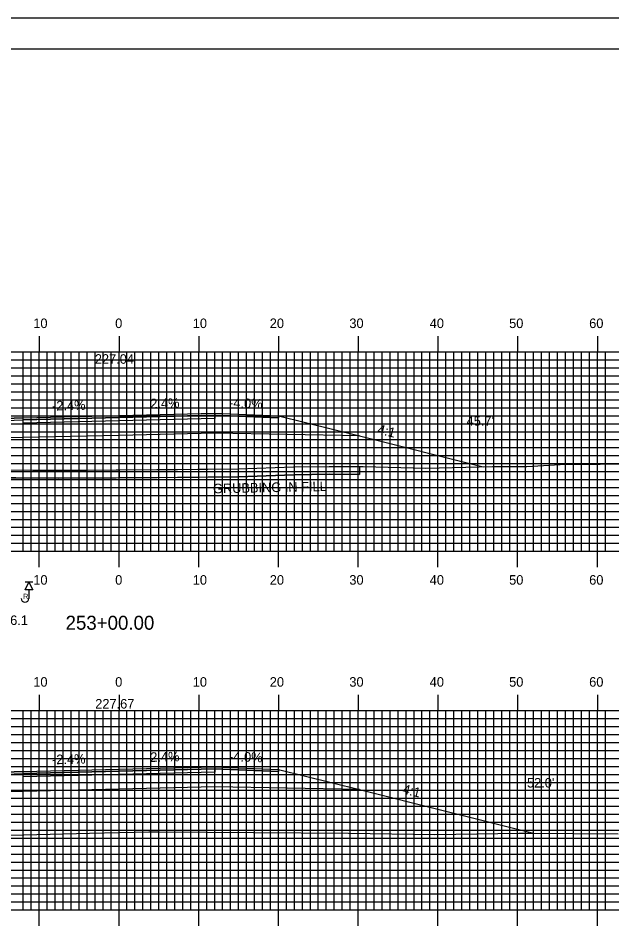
# Model space of a CAD drawing. Extents: x 1804290 to 1804634, y 442591 to 442811.
# Drawn here: x 1804443.5 to 1804518, y 442696.2 to 442810.5 of the extents above; entities that cross this region are included whole.
import ezdxf

# ---------------------------------------------------------------- set-up
doc = ezdxf.new("R2010")
doc.units = 0
for name, color, linetype in [('ANNOTATION', 7, 'Continuous'), ('BORDER', 7, 'Continuous'), ('BORING - REFUSAL', 7, 'Continuous'), ('D_Roadway_Centerline', 7, 'Continuous'), ('D_Roadway_Centerline_Text', 7, 'Continuous'), ('D_Roadway_Edge_Shoulder', 7, 'Continuous'), ('D_Roadway_Edge_TW', 7, 'Continuous'), ('D_Roadway_Pavement', 7, 'Continuous'), ('D_Roadway_SlopeLines', 7, 'Continuous'), ('D_Roadway_SubGrade', 7, 'Continuous'), ('D_Text_Standard', 7, 'Continuous'), ('GRUBBING IN FILL', 7, 'Continuous'), ('H_V ANNOTATION', 7, 'Continuous'), ('MAJOR', 7, 'Continuous'), ('MINOR', 7, 'Continuous'), ('PLOT BOUNDARY', 7, 'Continuous'), ('S_Roadway_Centerline', 7, 'Continuous')]:
    doc.layers.add(name, color=color, linetype=linetype)

msp = doc.modelspace()

# ---------------------------------------------------------------- linework, layer by layer
at = {"layer": 'BORDER'}
msp.add_lwpolyline([(1804306.57, 442596.67), (1804626.57, 442596.67), (1804626.57, 442806.67), (1804306.57, 442806.67)], close=True, dxfattribs=at)
at = {"layer": 'BORING - REFUSAL'}
for p, q in [((1804445.35, 442739.77), (1804444.39, 442739.77)), ((1804444.87, 442738.81), (1804444.87, 442737.75))]:
    msp.add_line(p, q, dxfattribs=at)
msp.add_lwpolyline([(1804444.87, 442739.77), (1804445.35, 442738.81), (1804444.39, 442738.81)], close=True, dxfattribs=at)
msp.add_arc((1804444.38, 442737.75), 0.485, 180, 0, dxfattribs=at)
at = {"layer": 'D_Roadway_Centerline'}
for points in [[(1804410.07, 442753.57), (1804424.17, 442757.1), (1804425.99, 442757.55), (1804436.17, 442760.1), (1804444.17, 442760.42), (1804456.17, 442760.71), (1804468.17, 442760.99), (1804476.17, 442760.67), (1804486.34, 442758.13), (1804501.85, 442754.25)], [(1804404.33, 442707.76), (1804424.17, 442712.72), (1804425.99, 442713.18), (1804436.17, 442715.72), (1804444.17, 442716.04), (1804456.17, 442716.33), (1804468.17, 442716.62), (1804476.17, 442716.3), (1804486.34, 442713.76), (1804508.15, 442708.3)]]:
    msp.add_lwpolyline(points, dxfattribs=at)
at = {"layer": 'D_Roadway_Edge_Shoulder'}
for points in [[(1804468.17, 442760.99), (1804476.17, 442760.67), (1804476.17, 442760.42), (1804468.17, 442760.74)], [(1804444.17, 442760.42), (1804436.17, 442760.1), (1804436.17, 442759.85), (1804444.17, 442760.17)], [(1804468.17, 442716.62), (1804476.17, 442716.3), (1804476.17, 442716.05), (1804468.17, 442716.37)], [(1804444.17, 442716.04), (1804436.17, 442715.72), (1804436.17, 442715.47), (1804444.17, 442715.79)]]:
    msp.add_lwpolyline(points, close=True, dxfattribs=at)
at = {"layer": 'D_Roadway_Edge_TW'}
for points in [[(1804444.17, 442760.17), (1804444.17, 442760.42), (1804456.17, 442760.71), (1804468.17, 442760.99), (1804468.17, 442760.74), (1804456.17, 442760.46)], [(1804444.17, 442715.79), (1804444.17, 442716.04), (1804456.17, 442716.33), (1804468.17, 442716.62), (1804468.17, 442716.37), (1804456.17, 442716.08)]]:
    msp.add_lwpolyline(points, close=True, dxfattribs=at)
at = {"layer": 'D_Roadway_Pavement'}
for points in [[(1804444.17, 442759.75), (1804444.17, 442760.17), (1804456.17, 442760.46), (1804468.17, 442760.74), (1804468.17, 442760.33), (1804456.17, 442760.04)], [(1804444.17, 442715.38), (1804444.17, 442715.79), (1804456.17, 442716.08), (1804468.17, 442716.37), (1804468.17, 442715.95), (1804456.17, 442715.66)]]:
    msp.add_lwpolyline(points, close=True, dxfattribs=at)
at = {"layer": 'D_Roadway_SlopeLines'}
for points in [[(1804476.17, 442760.67), (1804486.34, 442758.13), (1804501.85, 442754.25)], [(1804476.17, 442716.3), (1804486.34, 442713.76), (1804508.15, 442708.3)]]:
    msp.add_lwpolyline(points, dxfattribs=at)
at = {"layer": 'D_Roadway_SubGrade'}
for points in [[(1804444.17, 442757.92), (1804425.99, 442757.55), (1804436.17, 442760.1), (1804436.17, 442759.85), (1804444.17, 442760.17), (1804456.17, 442760.46), (1804468.17, 442760.74), (1804476.17, 442760.42), (1804476.17, 442760.67), (1804486.34, 442758.13), (1804468.17, 442758.49), (1804456.17, 442758.21)], [(1804444.17, 442713.54), (1804425.99, 442713.18), (1804436.17, 442715.72), (1804436.17, 442715.47), (1804444.17, 442715.79), (1804456.17, 442716.08), (1804468.17, 442716.37), (1804476.17, 442716.05), (1804476.17, 442716.3), (1804486.34, 442713.76), (1804468.17, 442714.12), (1804456.17, 442713.83)]]:
    msp.add_lwpolyline(points, close=True, dxfattribs=at)
at = {"layer": 'GRUBBING IN FILL'}
msp.add_line((1804486.34, 442754.29), (1804486.34, 442753.29), dxfattribs=at)
msp.add_line((1804486.34, 442754.29), (1804486.34, 442753.29), dxfattribs=at)
for points in [[(1804425.99, 442753.01), (1804425.99, 442754.01), (1804431.89, 442754.11), (1804437, 442753.99), (1804442.11, 442753.87), (1804445.35, 442753.85), (1804452.2, 442753.85), (1804456.17, 442753.87), (1804456.17, 442752.87), (1804452.2, 442752.85), (1804448.59, 442752.84), (1804445.34, 442752.85), (1804436.99, 442752.99), (1804431.89, 442753.11)], [(1804425.99, 442753.01), (1804425.99, 442754.01), (1804431.89, 442754.11), (1804437, 442753.99), (1804442.11, 442753.87), (1804445.35, 442753.85), (1804452.2, 442753.85), (1804456.17, 442753.87), (1804456.17, 442752.87), (1804452.2, 442752.85), (1804448.59, 442752.84), (1804445.34, 442752.85), (1804436.99, 442752.99), (1804431.89, 442753.11)], [(1804456.17, 442753.87), (1804463.49, 442753.94), (1804471.17, 442754.01), (1804478.07, 442754.25), (1804482.53, 442754.32), (1804484.66, 442754.31), (1804486.34, 442754.29), (1804486.34, 442753.29), (1804484.44, 442753.31), (1804482.54, 442753.32), (1804478.09, 442753.25), (1804474.64, 442753.13), (1804471.19, 442753.01), (1804463.51, 442752.94), (1804456.17, 442752.87)], [(1804456.17, 442753.87), (1804463.49, 442753.94), (1804471.17, 442754.01), (1804478.07, 442754.25), (1804482.53, 442754.32), (1804484.66, 442754.31), (1804486.34, 442754.29), (1804486.34, 442753.29), (1804484.44, 442753.31), (1804482.54, 442753.32), (1804478.09, 442753.25), (1804474.64, 442753.13), (1804471.19, 442753.01), (1804463.51, 442752.94), (1804456.17, 442752.87)]]:
    msp.add_lwpolyline(points, close=True, dxfattribs=at)
msp.add_lwpolyline([(1804425.99, 442753.01), (1804431.89, 442753.11), (1804442.1, 442752.87), (1804448.59, 442752.84), (1804455.82, 442752.87), (1804471.19, 442753.01), (1804478.09, 442753.25), (1804482.54, 442753.32), (1804486.34, 442753.29)], dxfattribs=at)
msp.add_lwpolyline([(1804425.99, 442753.01), (1804431.89, 442753.11), (1804442.1, 442752.87), (1804448.59, 442752.84), (1804455.82, 442752.87), (1804471.19, 442753.01), (1804478.09, 442753.25), (1804482.54, 442753.32), (1804486.34, 442753.29)], dxfattribs=at)
at = {"layer": 'MAJOR'}
for p, q in [((1804446.17, 442770.67), (1804446.17, 442768.67)), ((1804456.17, 442770.67), (1804456.17, 442768.67)), ((1804466.17, 442770.67), (1804466.17, 442768.67)), ((1804476.17, 442770.67), (1804476.17, 442768.67)), ((1804486.17, 442770.67), (1804486.17, 442768.67)), ((1804496.17, 442770.67), (1804496.17, 442768.67)), ((1804506.17, 442770.67), (1804506.17, 442768.67)), ((1804516.17, 442770.67), (1804516.17, 442768.67)), ((1804316.17, 442768.67), (1804596.17, 442768.67)), ((1804316.17, 442768.67), (1804596.17, 442768.67)), ((1804446.17, 442743.67), (1804446.17, 442768.67)), ((1804456.17, 442743.67), (1804456.17, 442768.67)), ((1804466.17, 442743.67), (1804466.17, 442768.67)), ((1804476.17, 442743.67), (1804476.17, 442768.67)), ((1804486.17, 442743.67), (1804486.17, 442768.67)), ((1804496.17, 442743.67), (1804496.17, 442768.67)), ((1804506.17, 442743.67), (1804506.17, 442768.67)), ((1804516.17, 442743.67), (1804516.17, 442768.67)), ((1804316.17, 442763.67), (1804596.17, 442763.67)), ((1804316.17, 442758.67), (1804596.17, 442758.67)), ((1804316.17, 442753.67), (1804596.17, 442753.67)), ((1804316.17, 442748.67), (1804596.17, 442748.67)), ((1804316.17, 442743.67), (1804596.17, 442743.67)), ((1804316.17, 442743.67), (1804596.17, 442743.67)), ((1804446.17, 442741.66), (1804446.17, 442743.67)), ((1804456.17, 442741.66), (1804456.17, 442743.67)), ((1804466.17, 442741.66), (1804466.17, 442743.67)), ((1804476.17, 442741.66), (1804476.17, 442743.67)), ((1804486.17, 442741.66), (1804486.17, 442743.67)), ((1804496.17, 442741.66), (1804496.17, 442743.67)), ((1804506.17, 442741.66), (1804506.17, 442743.67)), ((1804516.17, 442741.66), (1804516.17, 442743.67)), ((1804446.17, 442725.67), (1804446.17, 442723.67)), ((1804456.17, 442725.67), (1804456.17, 442723.67)), ((1804466.17, 442725.67), (1804466.17, 442723.67)), ((1804476.17, 442725.67), (1804476.17, 442723.67)), ((1804486.17, 442725.67), (1804486.17, 442723.67)), ((1804496.17, 442725.67), (1804496.17, 442723.67)), ((1804506.17, 442725.67), (1804506.17, 442723.67)), ((1804516.17, 442725.67), (1804516.17, 442723.67)), ((1804316.17, 442723.67), (1804596.17, 442723.67)), ((1804316.17, 442723.67), (1804596.17, 442723.67)), ((1804446.17, 442698.67), (1804446.17, 442723.67)), ((1804456.17, 442698.67), (1804456.17, 442723.67)), ((1804466.17, 442698.67), (1804466.17, 442723.67)), ((1804476.17, 442698.67), (1804476.17, 442723.67)), ((1804486.17, 442698.67), (1804486.17, 442723.67)), ((1804496.17, 442698.67), (1804496.17, 442723.67)), ((1804506.17, 442698.67), (1804506.17, 442723.67)), ((1804516.17, 442698.67), (1804516.17, 442723.67)), ((1804316.17, 442718.67), (1804596.17, 442718.67)), ((1804316.17, 442713.67), (1804596.17, 442713.67)), ((1804316.17, 442708.67), (1804596.17, 442708.67)), ((1804316.17, 442703.67), (1804596.17, 442703.67)), ((1804316.17, 442698.67), (1804596.17, 442698.67)), ((1804316.17, 442698.67), (1804596.17, 442698.67)), ((1804446.17, 442696.66), (1804446.17, 442698.67)), ((1804456.17, 442696.66), (1804456.17, 442698.67)), ((1804466.17, 442696.66), (1804466.17, 442698.67)), ((1804476.17, 442696.66), (1804476.17, 442698.67)), ((1804486.17, 442696.66), (1804486.17, 442698.67)), ((1804496.17, 442696.66), (1804496.17, 442698.67)), ((1804506.17, 442696.66), (1804506.17, 442698.67)), ((1804516.17, 442696.66), (1804516.17, 442698.67))]:
    msp.add_line(p, q, dxfattribs=at)
at = {"layer": 'MINOR'}
for p, q in [((1804316.17, 442767.67), (1804596.17, 442767.67)), ((1804444.17, 442743.67), (1804444.17, 442768.67)), ((1804445.17, 442743.67), (1804445.17, 442768.67)), ((1804447.17, 442743.67), (1804447.17, 442768.67)), ((1804448.17, 442743.67), (1804448.17, 442768.67)), ((1804449.17, 442743.67), (1804449.17, 442768.67)), ((1804450.17, 442743.67), (1804450.17, 442768.67)), ((1804451.17, 442743.67), (1804451.17, 442768.67)), ((1804452.17, 442743.67), (1804452.17, 442768.67)), ((1804453.17, 442743.67), (1804453.17, 442768.67)), ((1804454.17, 442743.67), (1804454.17, 442768.67)), ((1804455.17, 442743.67), (1804455.17, 442768.67)), ((1804457.17, 442743.67), (1804457.17, 442768.67)), ((1804458.17, 442743.67), (1804458.17, 442768.67)), ((1804459.17, 442743.67), (1804459.17, 442768.67)), ((1804460.17, 442743.67), (1804460.17, 442768.67)), ((1804461.17, 442743.67), (1804461.17, 442768.67)), ((1804462.17, 442743.67), (1804462.17, 442768.67)), ((1804463.17, 442743.67), (1804463.17, 442768.67)), ((1804464.17, 442743.67), (1804464.17, 442768.67)), ((1804465.17, 442743.67), (1804465.17, 442768.67)), ((1804467.17, 442743.67), (1804467.17, 442768.67)), ((1804468.17, 442743.67), (1804468.17, 442768.67)), ((1804469.17, 442743.67), (1804469.17, 442768.67)), ((1804470.17, 442743.67), (1804470.17, 442768.67)), ((1804471.17, 442743.67), (1804471.17, 442768.67)), ((1804472.17, 442743.67), (1804472.17, 442768.67)), ((1804473.17, 442743.67), (1804473.17, 442768.67)), ((1804474.17, 442743.67), (1804474.17, 442768.67)), ((1804475.17, 442743.67), (1804475.17, 442768.67)), ((1804477.17, 442743.67), (1804477.17, 442768.67)), ((1804478.17, 442743.67), (1804478.17, 442768.67)), ((1804479.17, 442743.67), (1804479.17, 442768.67)), ((1804480.17, 442743.67), (1804480.17, 442768.67)), ((1804481.17, 442743.67), (1804481.17, 442768.67)), ((1804482.17, 442743.67), (1804482.17, 442768.67)), ((1804483.17, 442743.67), (1804483.17, 442768.67)), ((1804484.17, 442743.67), (1804484.17, 442768.67)), ((1804485.17, 442743.67), (1804485.17, 442768.67)), ((1804487.17, 442743.67), (1804487.17, 442768.67)), ((1804488.17, 442743.67), (1804488.17, 442768.67)), ((1804489.17, 442743.67), (1804489.17, 442768.67)), ((1804490.17, 442743.67), (1804490.17, 442768.67)), ((1804491.17, 442743.67), (1804491.17, 442768.67)), ((1804492.17, 442743.67), (1804492.17, 442768.67)), ((1804493.17, 442743.67), (1804493.17, 442768.67)), ((1804494.17, 442743.67), (1804494.17, 442768.67)), ((1804495.17, 442743.67), (1804495.17, 442768.67)), ((1804497.17, 442743.67), (1804497.17, 442768.67)), ((1804498.17, 442743.67), (1804498.17, 442768.67)), ((1804499.17, 442743.67), (1804499.17, 442768.67)), ((1804500.17, 442743.67), (1804500.17, 442768.67)), ((1804501.17, 442743.67), (1804501.17, 442768.67)), ((1804502.17, 442743.67), (1804502.17, 442768.67)), ((1804503.17, 442743.67), (1804503.17, 442768.67)), ((1804504.17, 442743.67), (1804504.17, 442768.67)), ((1804505.17, 442743.67), (1804505.17, 442768.67)), ((1804507.17, 442743.67), (1804507.17, 442768.67)), ((1804508.17, 442743.67), (1804508.17, 442768.67)), ((1804509.17, 442743.67), (1804509.17, 442768.67)), ((1804510.17, 442743.67), (1804510.17, 442768.67)), ((1804511.17, 442743.67), (1804511.17, 442768.67)), ((1804512.17, 442743.67), (1804512.17, 442768.67)), ((1804513.17, 442743.67), (1804513.17, 442768.67)), ((1804514.17, 442743.67), (1804514.17, 442768.67)), ((1804515.17, 442743.67), (1804515.17, 442768.67)), ((1804517.17, 442743.67), (1804517.17, 442768.67)), ((1804316.17, 442766.67), (1804596.17, 442766.67)), ((1804316.17, 442765.67), (1804596.17, 442765.67)), ((1804316.17, 442764.67), (1804596.17, 442764.67)), ((1804316.17, 442762.67), (1804596.17, 442762.67)), ((1804316.17, 442761.67), (1804596.17, 442761.67)), ((1804316.17, 442760.67), (1804596.17, 442760.67)), ((1804316.17, 442759.67), (1804596.17, 442759.67)), ((1804316.17, 442757.67), (1804596.17, 442757.67)), ((1804316.17, 442756.67), (1804596.17, 442756.67)), ((1804316.17, 442755.67), (1804596.17, 442755.67)), ((1804316.17, 442754.67), (1804596.17, 442754.67)), ((1804316.17, 442752.67), (1804596.17, 442752.67)), ((1804316.17, 442751.67), (1804596.17, 442751.67)), ((1804316.17, 442750.67), (1804596.17, 442750.67)), ((1804316.17, 442749.67), (1804596.17, 442749.67)), ((1804316.17, 442747.67), (1804596.17, 442747.67)), ((1804316.17, 442746.67), (1804596.17, 442746.67)), ((1804316.17, 442745.67), (1804596.17, 442745.67)), ((1804316.17, 442744.67), (1804596.17, 442744.67)), ((1804444.17, 442698.67), (1804444.17, 442723.67)), ((1804445.17, 442698.67), (1804445.17, 442723.67)), ((1804447.17, 442698.67), (1804447.17, 442723.67)), ((1804448.17, 442698.67), (1804448.17, 442723.67)), ((1804449.17, 442698.67), (1804449.17, 442723.67)), ((1804450.17, 442698.67), (1804450.17, 442723.67)), ((1804451.17, 442698.67), (1804451.17, 442723.67)), ((1804452.17, 442698.67), (1804452.17, 442723.67)), ((1804453.17, 442698.67), (1804453.17, 442723.67)), ((1804454.17, 442698.67), (1804454.17, 442723.67)), ((1804455.17, 442698.67), (1804455.17, 442723.67)), ((1804457.17, 442698.67), (1804457.17, 442723.67)), ((1804458.17, 442698.67), (1804458.17, 442723.67)), ((1804459.17, 442698.67), (1804459.17, 442723.67)), ((1804460.17, 442698.67), (1804460.17, 442723.67)), ((1804461.17, 442698.67), (1804461.17, 442723.67)), ((1804462.17, 442698.67), (1804462.17, 442723.67)), ((1804463.17, 442698.67), (1804463.17, 442723.67)), ((1804464.17, 442698.67), (1804464.17, 442723.67)), ((1804465.17, 442698.67), (1804465.17, 442723.67)), ((1804467.17, 442698.67), (1804467.17, 442723.67)), ((1804468.17, 442698.67), (1804468.17, 442723.67)), ((1804469.17, 442698.67), (1804469.17, 442723.67)), ((1804470.17, 442698.67), (1804470.17, 442723.67)), ((1804471.17, 442698.67), (1804471.17, 442723.67)), ((1804472.17, 442698.67), (1804472.17, 442723.67)), ((1804473.17, 442698.67), (1804473.17, 442723.67)), ((1804474.17, 442698.67), (1804474.17, 442723.67)), ((1804475.17, 442698.67), (1804475.17, 442723.67)), ((1804477.17, 442698.67), (1804477.17, 442723.67)), ((1804478.17, 442698.67), (1804478.17, 442723.67)), ((1804479.17, 442698.67), (1804479.17, 442723.67)), ((1804480.17, 442698.67), (1804480.17, 442723.67)), ((1804481.17, 442698.67), (1804481.17, 442723.67)), ((1804482.17, 442698.67), (1804482.17, 442723.67)), ((1804483.17, 442698.67), (1804483.17, 442723.67)), ((1804484.17, 442698.67), (1804484.17, 442723.67)), ((1804485.17, 442698.67), (1804485.17, 442723.67)), ((1804487.17, 442698.67), (1804487.17, 442723.67)), ((1804488.17, 442698.67), (1804488.17, 442723.67)), ((1804489.17, 442698.67), (1804489.17, 442723.67)), ((1804490.17, 442698.67), (1804490.17, 442723.67)), ((1804491.17, 442698.67), (1804491.17, 442723.67)), ((1804492.17, 442698.67), (1804492.17, 442723.67)), ((1804493.17, 442698.67), (1804493.17, 442723.67)), ((1804494.17, 442698.67), (1804494.17, 442723.67)), ((1804495.17, 442698.67), (1804495.17, 442723.67)), ((1804497.17, 442698.67), (1804497.17, 442723.67)), ((1804498.17, 442698.67), (1804498.17, 442723.67)), ((1804499.17, 442698.67), (1804499.17, 442723.67)), ((1804500.17, 442698.67), (1804500.17, 442723.67)), ((1804501.17, 442698.67), (1804501.17, 442723.67)), ((1804502.17, 442698.67), (1804502.17, 442723.67)), ((1804503.17, 442698.67), (1804503.17, 442723.67)), ((1804504.17, 442698.67), (1804504.17, 442723.67)), ((1804505.17, 442698.67), (1804505.17, 442723.67)), ((1804507.17, 442698.67), (1804507.17, 442723.67)), ((1804508.17, 442698.67), (1804508.17, 442723.67)), ((1804509.17, 442698.67), (1804509.17, 442723.67)), ((1804510.17, 442698.67), (1804510.17, 442723.67)), ((1804511.17, 442698.67), (1804511.17, 442723.67)), ((1804512.17, 442698.67), (1804512.17, 442723.67)), ((1804513.17, 442698.67), (1804513.17, 442723.67)), ((1804514.17, 442698.67), (1804514.17, 442723.67)), ((1804515.17, 442698.67), (1804515.17, 442723.67)), ((1804517.17, 442698.67), (1804517.17, 442723.67)), ((1804316.17, 442722.67), (1804596.17, 442722.67)), ((1804316.17, 442721.67), (1804596.17, 442721.67)), ((1804316.17, 442720.67), (1804596.17, 442720.67)), ((1804316.17, 442719.67), (1804596.17, 442719.67)), ((1804316.17, 442717.67), (1804596.17, 442717.67)), ((1804316.17, 442716.67), (1804596.17, 442716.67)), ((1804316.17, 442715.67), (1804596.17, 442715.67)), ((1804316.17, 442714.67), (1804596.17, 442714.67)), ((1804316.17, 442712.67), (1804596.17, 442712.67)), ((1804316.17, 442711.67), (1804596.17, 442711.67)), ((1804316.17, 442710.67), (1804596.17, 442710.67)), ((1804316.17, 442709.67), (1804596.17, 442709.67)), ((1804316.17, 442707.67), (1804596.17, 442707.67)), ((1804316.17, 442706.67), (1804596.17, 442706.67)), ((1804316.17, 442705.67), (1804596.17, 442705.67)), ((1804316.17, 442704.67), (1804596.17, 442704.67)), ((1804316.17, 442702.67), (1804596.17, 442702.67)), ((1804316.17, 442701.67), (1804596.17, 442701.67)), ((1804316.17, 442700.67), (1804596.17, 442700.67)), ((1804316.17, 442699.67), (1804596.17, 442699.67))]:
    msp.add_line(p, q, dxfattribs=at)
at = {"layer": 'PLOT BOUNDARY'}
msp.add_lwpolyline([(1804290.38, 442590.55), (1804630.38, 442590.55), (1804630.38, 442810.55), (1804290.38, 442810.55)], close=True, dxfattribs=at)
at = {"layer": 'S_Roadway_Centerline'}
for points in [[(1804390.07, 442753.77), (1804394.91, 442753.68), (1804401.92, 442753.5), (1804409.8, 442753.56), (1804418.83, 442753.9), (1804431.89, 442754.11), (1804442.11, 442753.87), (1804448.59, 442753.84), (1804455.81, 442753.87), (1804471.17, 442754.01), (1804478.07, 442754.25), (1804482.53, 442754.32), (1804486.78, 442754.29), (1804494.66, 442754.11), (1804503.03, 442754.28), (1804507.3, 442754.28), (1804511.52, 442754.56), (1804526.57, 442754.69)], [(1804393.95, 442707.75), (1804402.91, 442707.77), (1804411.61, 442707.71), (1804416.48, 442707.71), (1804425.87, 442707.73), (1804436.37, 442707.91), (1804437.59, 442707.92), (1804452.47, 442708.28), (1804459.91, 442708.44), (1804461.13, 442708.46), (1804484.96, 442708.31), (1804495.8, 442708.13), (1804506.33, 442708.31), (1804507.56, 442708.31), (1804518.78, 442708.2)]]:
    msp.add_lwpolyline(points, dxfattribs=at)

# ---------------------------------------------------------------- texts
at = {"layer": 'ANNOTATION'}
for s, rotation, p in [('-2.4%', 1.3748, (1804447.79, 442761.31)), ('2.4%', 1.3748, (1804460.11, 442761.6)), ('-4.0%', 357.7094, (1804469.96, 442761.72)), ('4:1', 345.9638, (1804488.51, 442758.45)), ('2.4%', 1.3748, (1804460.11, 442717.23)), ('-4.0%', 357.7094, (1804469.96, 442717.35)), ('-2.4%', 1.3748, (1804447.79, 442716.93)), ('4:1', 345.9638, (1804491.66, 442713.29))]:
    msp.add_text(s, height=1.2, rotation=rotation, dxfattribs=at).set_placement(p)
at = {"layer": 'BORING - REFUSAL'}
msp.add_text('R', height=0.64, dxfattribs=at).set_placement((1804444.16, 442737.69))
msp.add_text('APPROX. ELEV. 206.1', height=1.2, rotation=359.8142, dxfattribs=at).set_placement((1804428.16, 442734.46))
at = {"layer": 'D_Roadway_Centerline'}
for s, p in [('C', (1804456.16, 442760.71)), ('L', (1804456.17, 442760.7)), ('C', (1804456.16, 442716.33)), ('L', (1804456.17, 442716.32))]:
    msp.add_text(s, height=0.0146, dxfattribs=at).set_placement(p)
at = {"layer": 'D_Roadway_Centerline_Text'}
for s, p in [('227.04', (1804453.14, 442767.19)), ('227.67', (1804453.19, 442723.93))]:
    msp.add_text(s, height=1.2, dxfattribs=at).set_placement(p)
at = {"layer": 'D_Text_Standard'}
for s, p in [("45.7'", (1804499.77, 442759.42)), ("52.0'", (1804507.34, 442714.02))]:
    msp.add_text(s, height=1.2, dxfattribs=at).set_placement(p)
at = {"layer": 'GRUBBING IN FILL'}
msp.add_text('GRUBBING IN FILL', height=1.2, rotation=1.1683, dxfattribs=at).set_placement((1804467.97, 442750.93))
at = {"layer": 'H_V ANNOTATION'}
for s, height, p in [('10', 1.2, (1804445.42, 442771.67)), ('0', 1.2, (1804455.69, 442771.67)), ('10', 1.2, (1804465.42, 442771.67)), ('20', 1.2, (1804475.08, 442771.67)), ('30', 1.2, (1804485.06, 442771.67)), ('40', 1.2, (1804495.14, 442771.67)), ('50', 1.2, (1804505.1, 442771.67)), ('60', 1.2, (1804515.14, 442771.67)), ('10', 1.2, (1804445.42, 442739.47)), ('0', 1.2, (1804455.69, 442739.47)), ('10', 1.2, (1804465.42, 442739.47)), ('20', 1.2, (1804475.08, 442739.47)), ('30', 1.2, (1804485.06, 442739.47)), ('40', 1.2, (1804495.14, 442739.47)), ('50', 1.2, (1804505.1, 442739.47)), ('60', 1.2, (1804515.14, 442739.47)), ('253+00.00', 1.75, (1804449.47, 442733.82)), ('10', 1.2, (1804445.42, 442726.67)), ('0', 1.2, (1804455.69, 442726.67)), ('10', 1.2, (1804465.42, 442726.67)), ('20', 1.2, (1804475.08, 442726.67)), ('30', 1.2, (1804485.06, 442726.67)), ('40', 1.2, (1804495.14, 442726.67)), ('50', 1.2, (1804505.1, 442726.67)), ('60', 1.2, (1804515.14, 442726.67))]:
    msp.add_text(s, height=height, dxfattribs=at).set_placement(p)

doc.saveas('drawing.dxf')
